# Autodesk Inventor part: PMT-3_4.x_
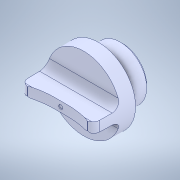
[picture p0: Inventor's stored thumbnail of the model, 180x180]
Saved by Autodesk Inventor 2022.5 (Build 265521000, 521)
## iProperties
Created: 2023-04
Part Number: PMT-3_4.x_
Material: Generic
Document SubType Name: Modeling
Designer: ImaoCorp
Density: 1 g/cm^3
Appearance: Default
Sending System: SOLIDWORKS 2021-2021301
MC: AMD64
MC_MODEL: Intel64 Family 6 Model 60 Stepping 3, GenuineIntel
OS: Windows_NT
FRU: Parasolid Version 32.1, build 255,  1- 1-2021
FORMAT: text
GUISE: transmit
KEY: PMT-3_4
FILE: PMT-3_4.x_t
DATE: Tue Apr  4 17:13:16 2023
Author: ImaoCorp
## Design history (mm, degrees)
feature "Base1"
node "ソリッド1"
